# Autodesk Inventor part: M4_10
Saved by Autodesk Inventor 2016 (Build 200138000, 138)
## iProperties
Created: 2016-01
Part Number: M4_10
Material: Generic
Document SubType Name: Modeling
Designer: John
Density: 1 g/cm^3
Appearance: Default
Author: John
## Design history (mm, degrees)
feature "CUT-EXTRUDE3"
body "Solid1"
